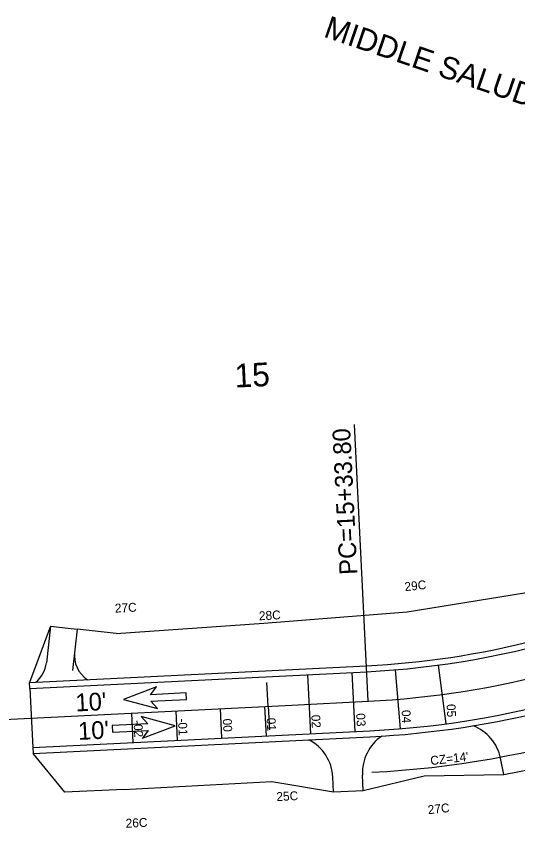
# Model space of a CAD drawing. Extents: x 1539042 to 1541327, y 1198578 to 1200629.
# Drawn here: x 1539807.9 to 1539977.1, y 1199334.3 to 1199608.4 of the extents above; entities that cross this region are included whole.
import ezdxf

# ---------------------------------------------------------------- set-up
doc = ezdxf.new("R2010")
doc.units = 0
for name, color, linetype in [('RD_HC_Cl', 7, 'Continuous'), ('RD_HC_CL_Rel', 7, 'Continuous'), ('RD_HC_Data', 7, 'Continuous'), ('RD_HC_Data_Tic', 7, 'Continuous'), ('RD_HC_TX_Sta50', 7, 'Continuous'), ('RD_PD_ALT1_TX', 7, 'Continuous'), ('RD_PD_CstnLmt', 7, 'Continuous'), ('RD_PD_CstnLmt_TX', 7, 'Continuous'), ('RD_PD_Driveway', 7, 'Continuous'), ('RD_PD_Final_TrvlWay', 7, 'Continuous'), ('RD_PD_Final_TX', 7, 'Continuous'), ('RD_PD_PaveShd', 7, 'Continuous'), ('RD_Sketch8', 7, 'Continuous')]:
    doc.layers.add(name, color=color, linetype=linetype)

msp = doc.modelspace()

# ---------------------------------------------------------------- linework, layer by layer
at = {"layer": 'RD_HC_Cl'}
msp.add_line((1539393.53, 1199350.4), (1539900.86, 1199375.77), dxfattribs=at)
at = {"layer": 'RD_HC_CL_Rel'}
msp.add_line((1539900.86, 1199375.77), (1539926.66, 1199377.06), dxfattribs=at)
msp.add_arc((1539911.68, 1199676.68), 300, 272.8619, 321.687, dxfattribs=at)
at = {"layer": 'RD_HC_Data'}
msp.add_line((1539926.66, 1199377.06), (1539921.99, 1199470.56), dxfattribs=at)
at = {"layer": 'RD_HC_Data_Tic'}
for q in [(1539892.51, 1199383.36), (1539893.31, 1199367.38)]:
    msp.add_line((1539892.91, 1199375.37), q, dxfattribs=at)
at = {"layer": 'RD_PD_ALT1_TX'}
for p, q in [((1539950.22, 1199389.25), (1539952.88, 1199369.43)), ((1539906.19, 1199386.04), (1539907.19, 1199366.07)), ((1539921.17, 1199386.79), (1539922.17, 1199366.82)), ((1539935.81, 1199387.69), (1539937.47, 1199367.76)), ((1539891.71, 1199375.31), (1539892.21, 1199365.32)), ((1539846.76, 1199373.06), (1539847.26, 1199363.07)), ((1539861.74, 1199373.81), (1539862.24, 1199363.82)), ((1539876.73, 1199374.56), (1539877.22, 1199364.57))]:
    msp.add_line(p, q, dxfattribs=at)
at = {"layer": 'RD_PD_CstnLmt'}
for p, q in [((1539939.79, 1199407.26), (1539984.44, 1199414.44)), ((1539891.5, 1199403.41), (1539939.79, 1199407.26)), ((1539819.48, 1199402.39), (1539812.41, 1199383.36)), ((1539841.61, 1199399.97), (1539891.5, 1199403.41)), ((1539841.61, 1199399.97), (1539828.45, 1199401.37)), ((1539824.27, 1199346.31), (1539813.61, 1199359.39)), ((1539844.25, 1199347.31), (1539894.18, 1199349.95)), ((1539894.18, 1199349.95), (1539914.99, 1199346.44)), ((1539924.98, 1199346.93), (1539945.58, 1199351.83)), ((1539945.58, 1199351.83), (1539972.43, 1199352.28)), ((1539844.25, 1199347.31), (1539824.27, 1199346.31))]:
    msp.add_line(p, q, dxfattribs=at)
at = {"layer": 'RD_PD_Driveway'}
for p, q in [((1539819.48, 1199402.39), (1539818.07, 1199390.02)), ((1539819.48, 1199402.39), (1539828.45, 1199401.37)), ((1539828.45, 1199401.37), (1539826.86, 1199387.43)), ((1539972.43, 1199352.28), (1539971.31, 1199357.79)), ((1539972.43, 1199352.28), (1539982.23, 1199354.27)), ((1539914.99, 1199346.44), (1539914.75, 1199351.43)), ((1539924.98, 1199346.93), (1539924.72, 1199352.14)), ((1539914.99, 1199346.44), (1539924.98, 1199346.93))]:
    msp.add_line(p, q, dxfattribs=at)
for centre, radius, start, end in [((1539837.51, 1199392.62), 10, 173.4885, 235.992), ((1539808.13, 1199391.16), 10, 309.7318, 353.4885), ((1539956.61, 1199354.8), 15, 11.4743, 68.6862), ((1539899.76, 1199350.68), 15, 2.8619, 62.9354), ((1539939.7, 1199352.89), 15, 124.2058, 182.8619)]:
    msp.add_arc(centre, radius, start, end, dxfattribs=at)
at = {"layer": 'RD_PD_Final_TrvlWay'}
for p, q in [((1539812.51, 1199381.36), (1539926.16, 1199387.04)), ((1539812.51, 1199381.36), (1539813.51, 1199361.39)), ((1539813.51, 1199361.39), (1539927.16, 1199367.07))]:
    msp.add_line(p, q, dxfattribs=at)
for radius, end in [(290, 301.8034), (310, 301.6792)]:
    msp.add_arc((1539911.68, 1199676.68), radius, 272.8619, end, dxfattribs=at)
at = {"layer": 'RD_PD_Final_TX'}
for p, q in [((1539855.19, 1199381.93), (1539844.14, 1199377.7)), ((1539853.22, 1199379.28), (1539855.19, 1199381.93)), ((1539844.14, 1199377.7), (1539855.56, 1199374.59)), ((1539865.21, 1199379.88), (1539853.22, 1199379.28)), ((1539853.33, 1199377.03), (1539865.32, 1199377.63)), ((1539865.32, 1199377.63), (1539865.21, 1199379.88)), ((1539855.56, 1199374.59), (1539853.33, 1199377.03)), ((1539861.51, 1199368.79), (1539850.09, 1199371.9)), ((1539850.09, 1199371.9), (1539852.32, 1199369.45)), ((1539852.32, 1199369.45), (1539840.33, 1199368.86)), ((1539840.33, 1199368.86), (1539840.44, 1199366.61)), ((1539840.44, 1199366.61), (1539852.43, 1199367.21)), ((1539850.46, 1199364.56), (1539861.51, 1199368.79)), ((1539852.43, 1199367.21), (1539850.46, 1199364.56))]:
    msp.add_line(p, q, dxfattribs=at)
at = {"layer": 'RD_PD_PaveShd'}
for p, q in [((1539812.41, 1199383.36), (1539926.06, 1199389.04)), ((1539812.51, 1199381.36), (1539812.41, 1199383.36)), ((1539813.61, 1199359.39), (1539927.26, 1199365.07)), ((1539813.51, 1199361.39), (1539813.61, 1199359.39))]:
    msp.add_line(p, q, dxfattribs=at)
for radius, end in [(288, 295.5911), (312, 296.0265)]:
    msp.add_arc((1539911.68, 1199676.68), radius, 272.8619, end, dxfattribs=at)
at = {"layer": 'RD_Sketch8'}
msp.add_arc((1539911.68, 1199676.68), 324, 272.8619, 301.5493, dxfattribs=at)

# ---------------------------------------------------------------- texts
at = {"layer": 'RD_HC_Data'}
for s, height, rotation, p in [('MIDDLE SALUDA RIVER', 7.5, 341.1022, (1539911.29, 1199601.54)), ('PC=15+33.80', 6, 92.8619, (1539923.02, 1199419.91))]:
    msp.add_text(s, height=height, rotation=rotation, dxfattribs=at).set_placement(p)
at = {"layer": 'RD_HC_TX_Sta50'}
msp.add_text('15', height=8, rotation=2.8619, dxfattribs=at).set_placement((1539881.76, 1199482.95))
at = {"layer": 'RD_PD_ALT1_TX'}
for s, p in [('05', (1539953.11, 1199376.05)), ('02', (1539907.45, 1199372.42)), ('03', (1539922.6, 1199372.93)), ('04', (1539937.92, 1199374.04)), ('-02', (1539847.47, 1199370.61)), ('-01', (1539862.46, 1199371.18)), ('00', (1539877.59, 1199371.12)), ('01', (1539892.4, 1199371.41))]:
    msp.add_text(s, height=3, rotation=272.8619, dxfattribs=at).set_placement(p)
at = {"layer": 'RD_PD_CstnLmt_TX'}
for s, rotation, p in [('29C', 5.9561, (1539939.07, 1199414.22)), ('27C', 2.8619, (1539841.26, 1199406.97)), ('28C', 2.8619, (1539889.86, 1199404.39)), ('25C', 2.8619, (1539895.76, 1199343.34)), ('27C', 5.9561, (1539946.92, 1199338.9)), ('26C', 2.8619, (1539844.9, 1199334.33))]:
    msp.add_text(s, height=3, rotation=rotation, dxfattribs=at).set_placement(p)
at = {"layer": 'RD_PD_Final_TX'}
for p in [(1539828.03, 1199373.59), (1539828.89, 1199363.98)]:
    msp.add_text("10'", height=6, rotation=2.862, dxfattribs=at).set_placement(p)
at = {"layer": 'RD_Sketch8'}
msp.add_text("CZ=14'", height=3, rotation=6.498, dxfattribs=at).set_placement((1539947.8, 1199355.48))

doc.saveas('drawing.dxf')
